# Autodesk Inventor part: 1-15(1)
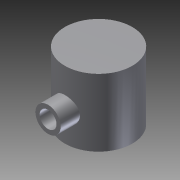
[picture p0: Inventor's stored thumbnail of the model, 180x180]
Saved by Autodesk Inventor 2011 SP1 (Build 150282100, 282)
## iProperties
Created: 2014-02
Part Number: 1-15(1)
Document SubType Name: Modeling
Designer: Administrator
Density: 1 g/cm^3
Author: Administrator
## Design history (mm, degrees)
sketch "草图1"
  geometry: C1 r 8 at (0, 0); 1 further point
  constraints: 1 centre point, 1 coincident
  dimensions: "d0" = 16 diameter of C1
extrude "拉伸1" new body sketch "草图1" distance "d1" = 16; taper "d2" = 0 deg
sketch "草图2"
  geometry: C1 r 8 at (0, 0) reference; C2 r 6 at (0, 0)
  constraints: 1 centre point, 1 coincident
  dimensions: "d3" = 12 diameter of C2
extrude "拉伸2" cut sketch "草图2" distance "d4" = 14; taper "d5" = 0 deg
node "工作平面1"
sketch "草图3"
  geometry: L1 (-6, 14)-(6, 14) reference; L2 (-8, 0)-(8, 0) reference; L3 (-6, 0)-(-6, 14) reference; L4 (6, 0)-(6, 14) reference; C1 r 3 at (0, 7); 1 further point
  constraints: 1 centre point
  dimensions: "d7" = 6 diameter of C1
extrude "拉伸3" join sketch "草图3" stored distance "d8" = 14; taper "d9" = 0 deg
sketch "草图4"
  geometry: C1 r 3 at (0, 0) reference; C2 r 2 at (0, 0); 1 further point
  constraints: 1 centre point, 1 coincident
  dimensions: "d10" = 4 diameter of C2
extrude "拉伸4" cut sketch "草图4" stored distance "d11" = 14; taper "d12" = 0 deg
node "实体1"
other parameters: "d6" = -12
